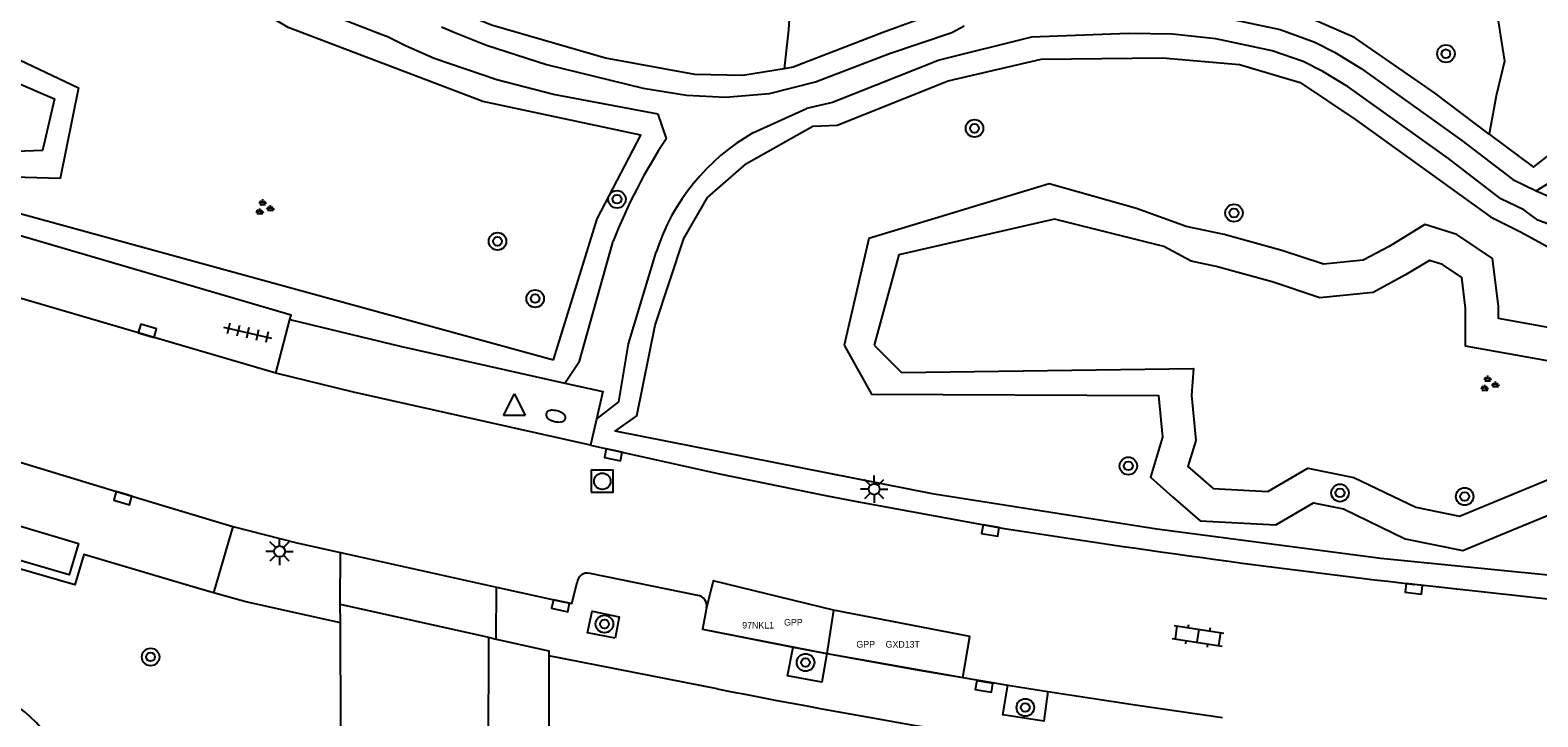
# Model space of a CAD drawing. Extents: x 132999 to 136000, y 398499 to 400501.
# Drawn here: x 133852.9 to 133921.6, y 399065.7 to 399097 of the extents above; entities that cross this region are included whole.
import ezdxf

# ---------------------------------------------------------------- set-up
doc = ezdxf.new("R2010")
doc.units = 0
for name, color, linetype in [('bp-anno-kenteken', 7, 'Continuous'), ('bp-grn-parkeervak', 7, 'Continuous'), ('gg-bbg-abri', 7, 'Continuous'), ('gg-knt-verharding', 7, 'Continuous'), ('gg-knt-verharding nz', 7, 'Continuous'), ('gt-grn-groengrens', 7, 'Continuous'), ('gt-grn-weggrens', 7, 'Continuous'), ('gt-symb-boom', 7, 'Continuous'), ('gt-symb-brandkraan', 7, 'Continuous'), ('gt-symb-groenvak', 7, 'Continuous'), ('gt-symb-klinker verharding', 7, 'Continuous'), ('gt-symb-kolk', 7, 'Continuous'), ('gt-symb-lichtmast', 7, 'Continuous'), ('gt-symb-rioolschacht', 7, 'Continuous'), ('gt-symb-tegel verharding', 7, 'Continuous'), ('gt-symb-waterafsluiter', 7, 'Continuous'), ('kenmerkpunt gehandicapten parkeerplaats', 7, 'Continuous')]:
    doc.layers.add(name, color=color, linetype=linetype)

# ---------------------------------------------------------------- blocks, each defined once
blk = doc.blocks.new('gt0-BOOM')
at = {"layer": 'gt-symb-boom'}
for radius in [0.4, 0.2]:
    blk.add_circle((0, 0), radius, dxfattribs=at)
blk = doc.blocks.new('gt0-GRVAK')
at = {"layer": 'gt-symb-groenvak'}
for p, q in [((-0.11, 0.189), (-0.228, 0.24)), ((-0.182, 0.153), (0.088, 0.153)), ((-0.091, 0.211), (-0.156, 0.322)), ((-0.047, 0.214), (-0.047, 0.393)), ((-0.004, 0.211), (0.061, 0.322)), ((0.015, 0.189), (0.133, 0.24)), ((0.262, -0.052), (0.197, 0.059)), ((0.305, -0.049), (0.305, 0.13)), ((0.349, -0.052), (0.414, 0.059)), ((-0.245, -0.228), (-0.363, -0.177)), ((-0.318, -0.264), (-0.047, -0.264)), ((-0.226, -0.206), (-0.291, -0.095)), ((-0.183, -0.203), (-0.183, -0.024)), ((-0.139, -0.206), (-0.074, -0.095)), ((-0.12, -0.228), (-0.002, -0.177)), ((0.243, -0.074), (0.125, -0.023)), ((0.17, -0.11), (0.441, -0.11)), ((0.368, -0.074), (0.486, -0.023))]:
    blk.add_line(p, q, dxfattribs=at)
blk = doc.blocks.new('gt0-BR')
at = {"layer": 'gt-symb-brandkraan'}
for centre, radius, start, end in [((-0.244, 0), 0.206, 107.56694, 252.43307), ((0.599, -2.664), 3, 106.89205, 107.56694), ((0, -0.691), 0.938, 73.10799, 106.89205), ((-0.599, -2.664), 3, 72.43309, 73.10799), ((0.244, 0), 0.206, 287.56695, 72.43309), ((0.599, 2.664), 3, 252.43307, 253.10797), ((0, 0.691), 0.938, 253.10797, 286.89206), ((-0.599, 2.664), 3, 286.89206, 287.56695)]:
    blk.add_arc(centre, radius, start, end, dxfattribs=at)
blk = doc.blocks.new('gt0-WAFSL')
at = {"layer": 'gt-symb-waterafsluiter'}
for p, q in [((-0.5, -0.333), (0, 0.667)), ((0, 0.667), (0.5, -0.333)), ((0.5, -0.333), (-0.5, -0.333))]:
    blk.add_line(p, q, dxfattribs=at)
blk = doc.blocks.new('gt0-KOLK')
at = {"layer": 'gt-symb-kolk'}
blk.add_lwpolyline([(0, 0), (0.375, 0), (0.375, 0.4), (-0.375, 0.4), (-0.375, 0), (0, 0)], dxfattribs=at)
blk = doc.blocks.new('gt0-TEG1')
at = {"layer": 'gt-symb-tegel verharding'}
for p, q in [((-1.125, 0), (1.125, 0)), ((-0.9, -0.25), (-0.9, 0.25)), ((-0.45, -0.25), (-0.45, 0.25)), ((0, -0.25), (0, 0.25)), ((0.45, -0.25), (0.45, 0.25)), ((0.9, -0.25), (0.9, 0.25))]:
    blk.add_line(p, q, dxfattribs=at)
blk = doc.blocks.new('gt0-LMAST')
at = {"layer": 'gt-symb-lichtmast'}
for p, q in [((-0.182, 0.173), (-0.447, 0.438)), ((-0.005, 0.246), (-0.005, 0.621)), ((0.172, 0.173), (0.437, 0.438)), ((-0.255, -0.004), (-0.63, -0.004)), ((-0.182, -0.181), (-0.447, -0.446)), ((-0.005, -0.254), (-0.005, -0.629)), ((0.437, -0.446), (0.172, -0.181)), ((0.245, -0.004), (0.62, -0.004))]:
    blk.add_line(p, q, dxfattribs=at)
blk.add_circle((-0.005, -0.004), 0.25, dxfattribs=at)
blk = doc.blocks.new('gt0-RS')
at = {"layer": 'gt-symb-rioolschacht'}
blk.add_lwpolyline([(-0.5, -0.5), (0.5, -0.5), (0.5, 0.5), (-0.5, 0.5)], close=True, dxfattribs=at)
blk.add_circle((0, 0), 0.375, dxfattribs=at)
blk = doc.blocks.new('gt0-KL1')
at = {"layer": 'gt-symb-klinker verharding'}
for p, q in [((-1.15, 0.3), (1.15, 0.3)), ((-1, -0.3), (-1, 0.3)), ((-0.5, 0.3), (-0.5, 0.45)), ((0, -0.3), (0, 0.3)), ((0.5, 0.3), (0.5, 0.45)), ((1, -0.3), (1, 0.3)), ((-1.15, -0.3), (1.15, -0.3)), ((-0.5, -0.45), (-0.5, -0.3)), ((0.5, -0.45), (0.5, -0.3))]:
    blk.add_line(p, q, dxfattribs=at)

msp = doc.modelspace()

# ---------------------------------------------------------------- linework, layer by layer
at = {"layer": 'bp-grn-parkeervak'}
msp.add_line((133889.491, 399070.606), (133889.183, 399068.636), dxfattribs=at)
for points in [[(133889.491, 399070.606), (133884.005, 399071.945), (133883.703, 399070.709), (133883.508, 399069.736), (133889.183, 399068.636)], [(133889.183, 399068.636), (133895.378, 399067.541), (133895.694, 399069.403), (133889.491, 399070.606)]]:
    msp.add_lwpolyline(points, dxfattribs=at)
at = {"layer": 'gg-bbg-abri'}
msp.add_lwpolyline([(133850.896, 399073.311), (133851.316, 399074.763), (133855.081, 399073.653), (133854.657, 399072.214), (133850.896, 399073.311)], dxfattribs=at)
at = {"layer": 'gg-knt-verharding'}
for p, q in [((133866.835, 399097.647), (133869.065, 399096.792)), ((133881.879, 399092.107), (133881.492, 399093.219)), ((133885.814, 399092.361), (133888.247, 399093.482)), ((133864.079, 399081.411), (133846.497, 399086.552)), ((133878.685, 399079.314), (133878.414, 399078.127)), ((133867.013, 399073.234), (133874.131, 399071.657)), ((133883.3, 399071.283), (133878.393, 399072.28)), ((133883.703, 399070.709), (133883.508, 399069.736)), ((133867.042, 399065.274), (133867.013, 399070.023)), ((133883.508, 399069.736), (133887.645, 399068.926)), ((133873.762, 399069.374), (133873.733, 399057.132)), ((133887.645, 399068.926), (133889.183, 399068.636)), ((133876.519, 399068.524), (133876.5, 399056.558)), ((133884.177, 399067.021), (133876.519, 399068.524)), ((133895.378, 399067.541), (133897.429, 399067.193)), ((133897.429, 399067.193), (133899.252, 399066.899))]:
    msp.add_line(p, q, dxfattribs=at)
for points in [[(133921.501, 399089.721), (133922.687, 399090.457), (133925.369, 399092.662), (133926.675, 399094.18), (133927.655, 399095.762), (133929.6, 399099.569), (133930.399, 399101.404), (133931.64, 399103.48), (133931.896, 399104.444), (133931.638, 399104.778), (133929.891, 399105.798), (133927.159, 399107.039), (133926.214, 399107.655), (133923.095, 399110.196), (133922.06, 399111.131), (133918.165, 399115.091), (133916.819, 399116.564), (133915.032, 399119.086)], [(133897.673, 399097.896), (133898.436, 399097.743), (133902.997, 399097.924), (133905.122, 399097.877), (133907.108, 399097.647), (133909.84, 399097.07), (133911.418, 399096.494), (133912.314, 399096.045), (133913.534, 399095.298), (133918.12, 399092.019), (133920.435, 399090.231), (133921.501, 399089.721)], [(133871.626, 399097.192), (133872.23, 399096.934), (133873.674, 399096.362), (133876.409, 399095.487), (133880.812, 399094.396), (133882.788, 399094.085), (133884.57, 399093.991), (133886.57, 399094.155), (133888.665, 399094.688), (133892.031, 399095.983), (133894.875, 399096.935), (133895.436, 399097.24)], [(133881.492, 399093.219), (133876.721, 399094.119), (133874.138, 399094.775), (133871.284, 399095.756), (133869.984, 399096.336), (133869.065, 399096.792)], [(133922.515, 399088.042), (133921.575, 399088.385), (133920.94, 399088.858), (133919.897, 399089.356), (133917.508, 399091.202), (133912.936, 399094.467), (133911.78, 399095.168), (133910.882, 399095.61), (133909.471, 399096.109), (133906.909, 399096.643), (133904.927, 399096.864), (133902.929, 399096.901), (133898.513, 399096.72), (133894.296, 399095.678), (133889.439, 399093.741), (133888.247, 399093.482)], [(133864.705, 399083.854), (133864.777, 399084.053), (133847.293, 399089.174)], [(133877.245, 399080.958), (133877.905, 399081.952), (133879.446, 399087.426)], [(133878.685, 399079.314), (133879.703, 399080.111), (133880.146, 399082.74), (133881.403, 399086.927)], [(133864.705, 399083.854), (133869.734, 399082.644), (133877.245, 399080.958)], [(133878.414, 399078.127), (133867.607, 399080.54), (133864.079, 399081.411)], [(133877.245, 399080.958), (133878.973, 399080.57), (133878.685, 399079.314)], [(133844.575, 399079.744), (133857.159, 399075.904), (133862.116, 399074.418)], [(133878.414, 399078.127), (133884.297, 399076.823), (133889.113, 399075.836), (133890.551, 399075.555), (133896.666, 399074.433)], [(133861.24, 399071.399), (133860.144, 399071.712), (133855.33, 399073.151), (133854.915, 399071.761), (133850.436, 399073.055), (133850.837, 399074.442), (133843.683, 399076.544)], [(133862.116, 399074.418), (133865.027, 399073.674), (133867.013, 399073.234)], [(133874.131, 399071.657), (133877.093, 399071.001), (133877.567, 399070.909), (133877.806, 399071.863)], [(133954.88, 399068.478), (133934.138, 399070.044), (133922.449, 399071.068), (133915.955, 399071.781)], [(133867.013, 399070.023), (133862.702, 399070.982), (133861.24, 399071.399)], [(133879.53, 399069.325), (133878.277, 399069.575), (133878.483, 399070.568), (133879.725, 399070.3), (133879.53, 399069.325)], [(133889.183, 399068.636), (133888.955, 399067.318), (133887.382, 399067.619), (133887.645, 399068.926)], [(133889.183, 399068.636), (133893.3, 399067.894), (133895.378, 399067.541)], [(133899.252, 399066.899), (133899.073, 399065.547), (133897.2, 399065.842), (133897.429, 399067.193)], [(133899.252, 399066.899), (133903.225, 399066.288), (133907.21, 399065.717)]]:
    msp.add_lwpolyline(points, dxfattribs=at)
for centre, radius, start, end in [((133890.572, 399083.991), 9.627, 119.61773, 162.24697), ((133901.546, 399078.912), 23.684, 146.14176, 158.93096), ((133967.196, 399515.953), 447.118, 260.924, 263.41923), ((133878.265, 399071.839), 0.459, 73.76449, 177.01486), ((133883.225, 399070.802), 0.487, 349.00362, 81.14104), ((133848.565, 399061.068), 6.365, 28.89671, 76.92106), ((133958.567, 399446.142), 386.351, 258.89859, 265.48221)]:
    msp.add_arc(centre, radius, start, end, dxfattribs=at)
at = {"layer": 'gg-knt-verharding nz'}
for p, q in [((133864.079, 399081.411), (133864.705, 399083.854)), ((133862.116, 399074.418), (133861.24, 399071.399)), ((133867.012, 399070.886), (133873.762, 399069.374)), ((133867.013, 399070.023), (133867.012, 399070.886)), ((133873.762, 399069.374), (133874.12, 399069.292))]:
    msp.add_line(p, q, dxfattribs=at)
for points in [[(133895.378, 399067.541), (133895.694, 399069.403), (133889.491, 399070.606), (133884.005, 399071.945), (133883.703, 399070.709)], [(133874.12, 399069.292), (133876.517, 399068.747), (133876.519, 399068.524)]]:
    msp.add_lwpolyline(points, dxfattribs=at)
at = {"layer": 'gt-grn-groengrens'}
for points in [[(133887.235, 399095.286), (133885.35, 399094.978), (133883.17, 399095.02), (133879.092, 399095.765), (133873.902, 399097.273), (133869.956, 399098.914), (133864.295, 399101.699), (133861.019, 399103.409), (133855.372, 399109.338), (133866.753, 399122.601), (133867.943, 399122.167), (133871.145, 399119.282), (133873.261, 399117.771), (133877.442, 399115.532), (133882.723, 399113.278), (133884.327, 399112.636), (133887.472, 399112.081), (133891.7, 399111.842), (133896.339, 399112.035), (133894.881, 399109.023), (133894.591, 399108.058)], [(133919.367, 399092.308), (133921.379, 399090.793), (133924.611, 399093.339), (133925.79, 399094.56), (133926.777, 399096.147), (133929.025, 399100.689), (133930.222, 399103.152), (133930.835, 399104.027), (133926.408, 399106.284), (133921.594, 399110.109), (133916.808, 399115.072), (133914.751, 399117.818), (133910.322, 399115.225), (133907.412, 399113.675), (133905.074, 399112.701)], [(133894.591, 399108.058), (133893.922, 399105.829), (133893.922, 399102.21), (133894.612, 399097.991), (133891.773, 399096.951), (133887.646, 399095.354), (133887.235, 399095.286)], [(133894.591, 399108.058), (133892.961, 399105.858), (133892.508, 399104.136), (133889.517, 399103.229), (133888.158, 399102.232), (133887.614, 399100.057), (133887.433, 399097.067), (133887.235, 399095.286)], [(133876.724, 399082.012), (133878.713, 399088.439), (133880.703, 399092.265), (133873.51, 399093.795), (133864.634, 399097.162), (133860.043, 399099.917), (133856.982, 399102.977), (133853.31, 399106.038), (133851.779, 399104.967), (133846.729, 399099.304), (133841.067, 399091.806), (133876.724, 399082.012)], [(133909.16, 399100.172), (133914.759, 399100.646), (133916.725, 399099.952), (133919.617, 399098.449), (133920.057, 399095.635), (133919.683, 399094.048), (133919.367, 399092.308)], [(133919.367, 399092.308), (133916.877, 399094.183), (133913.223, 399096.714), (133910.538, 399097.88), (133906.946, 399098.767), (133905.333, 399098.863)], [(133845.308, 399092.17), (133848.308, 399095.354), (133850.066, 399095.268), (133852.103, 399095.834), (133855.08, 399094.424), (133854.252, 399090.286), (133849.454, 399090.416), (133845.308, 399092.17)], [(133927.386, 399071.678), (133914.422, 399072.955), (133904.214, 399074.295), (133894.072, 399075.889), (133879.535, 399078.77), (133880.518, 399079.461), (133881.364, 399083.604), (133882.658, 399087.548), (133883.739, 399089.425), (133885.517, 399090.974), (133888.549, 399092.664), (133889.658, 399092.717), (133894.709, 399094.743), (133898.944, 399095.725), (133904.481, 399095.787), (133907.977, 399095.48), (133910.744, 399094.656), (133913.291, 399092.958), (133919.428, 399088.535), (133920.819, 399087.839), (133924.756, 399085.68)], [(133847.056, 399092.53), (133848.72, 399094.332), (133849.829, 399094.194), (133852.048, 399094.749), (133853.99, 399093.916), (133853.435, 399091.559), (133849.829, 399091.42), (133847.056, 399092.53)], [(133927.019, 399082.603), (133919.787, 399083.898), (133919.787, 399084.47), (133919.515, 399086.644), (133917.884, 399087.732), (133916.434, 399088.185), (133914.802, 399087.188), (133913.624, 399086.554), (133911.812, 399086.373), (133909.909, 399087.007), (133907.28, 399087.732), (133905.558, 399088.095), (133903.295, 399088.921), (133899.31, 399090.042), (133891.09, 399087.551), (133889.969, 399082.694)], [(133926.611, 399081.152), (133918.287, 399082.643), (133918.287, 399084.376), (133918.112, 399085.777), (133917.231, 399086.365), (133916.635, 399086.551), (133915.549, 399085.887), (133914.071, 399085.091), (133911.642, 399084.848), (133909.472, 399085.572), (133906.926, 399086.274), (133905.786, 399086.514), (133904.541, 399087.178), (133899.559, 399088.423), (133892.46, 399086.804), (133891.339, 399082.694)], [(133889.969, 399082.694), (133891.214, 399080.452), (133904.29, 399080.391), (133904.471, 399078.488), (133903.927, 399076.676), (133904.924, 399075.769), (133906.193, 399074.682), (133909.637, 399074.501), (133911.359, 399075.497), (133912.718, 399075.225), (133915.527, 399073.866), (133918.155, 399073.322), (133919.877, 399074.047), (133926.325, 399076.704)], [(133891.339, 399082.694), (133892.584, 399081.448), (133905.889, 399081.624), (133905.795, 399080.405), (133905.992, 399078.338), (133905.635, 399077.15), (133906.781, 399076.153), (133909.271, 399076.022), (133911.097, 399077.079), (133913.199, 399076.659), (133916.013, 399075.297), (133918.003, 399074.886), (133926.871, 399078.552)]]:
    msp.add_lwpolyline(points, dxfattribs=at)
at = {"layer": 'gt-grn-weggrens'}
for p, q in [((133921.501, 399089.721), (133923.048, 399089.051)), ((133867.012, 399070.886), (133867.013, 399073.234)), ((133874.12, 399069.292), (133874.131, 399071.657))]:
    msp.add_line(p, q, dxfattribs=at)

# ---------------------------------------------------------------- block references
at = {"layer": 'gt-symb-boom'}
for p in [(133917.391, 399095.972), (133895.909, 399092.571), (133879.62, 399089.337), (133907.732, 399088.712), (133874.176, 399087.42), (133875.889, 399084.809), (133902.919, 399077.182), (133912.563, 399075.952), (133918.244, 399075.79), (133879.047, 399069.977), (133858.367, 399068.475), (133888.211, 399068.222), (133898.223, 399066.171)]:
    msp.add_blockref('gt0-BOOM', p, dxfattribs=at)
at = {"layer": 'gt-symb-brandkraan', "rotation": 166.17220496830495}
msp.add_blockref('gt0-BR', (133876.828, 399079.451), dxfattribs=at)
at = {"layer": 'gt-symb-groenvak'}
for p in [(133863.521, 399088.945), (133919.34, 399080.907)]:
    msp.add_blockref('gt0-GRVAK', p, dxfattribs=at)
at = {"layer": 'gt-symb-klinker verharding', "rotation": -8.6242287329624}
msp.add_blockref('gt0-KL1', (133906.095, 399069.44), dxfattribs=at)
at = {"layer": 'gt-symb-kolk'}
for p, rotation in [((133858.166, 399083.149), -16.38630566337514), ((133879.495, 399077.88), 168.11724113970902), ((133857.159, 399075.904), 163.32270606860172), ((133896.666, 399074.433), 170.15137761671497), ((133915.955, 399071.781), 173.3939658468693), ((133877.093, 399071.001), 167.52092819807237), ((133896.378, 399067.327), 170.33049474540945)]:
    msp.add_blockref('gt0-KOLK', p, dxfattribs=dict(at, rotation=rotation))
at = {"layer": 'gt-symb-lichtmast'}
for p in [(133891.342, 399076.126), (133864.249, 399073.288)]:
    msp.add_blockref('gt0-LMAST', p, dxfattribs=at)
at = {"layer": 'gt-symb-rioolschacht'}
msp.add_blockref('gt0-RS', (133878.949, 399076.483), dxfattribs=at)
at = {"layer": 'gt-symb-tegel verharding', "rotation": 167.1728765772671}
msp.add_blockref('gt0-TEG1', (133862.795, 399083.245), dxfattribs=at)
at = {"layer": 'gt-symb-waterafsluiter'}
msp.add_blockref('gt0-WAFSL', (133874.941, 399079.808), dxfattribs=at)

# ---------------------------------------------------------------- texts
at = {"layer": 'bp-anno-kenteken'}
for s, p in [('97NKL1', (133885.326, 399069.771)), ('GXD13T', (133891.86, 399068.9))]:
    msp.add_text(s, height=0.3, dxfattribs=at).set_placement(p)
at = {"layer": 'kenmerkpunt gehandicapten parkeerplaats'}
for p in [(133887.232, 399069.906), (133890.528, 399068.901)]:
    msp.add_text('GPP', height=0.3, dxfattribs=at).set_placement(p)

doc.saveas('drawing.dxf')
